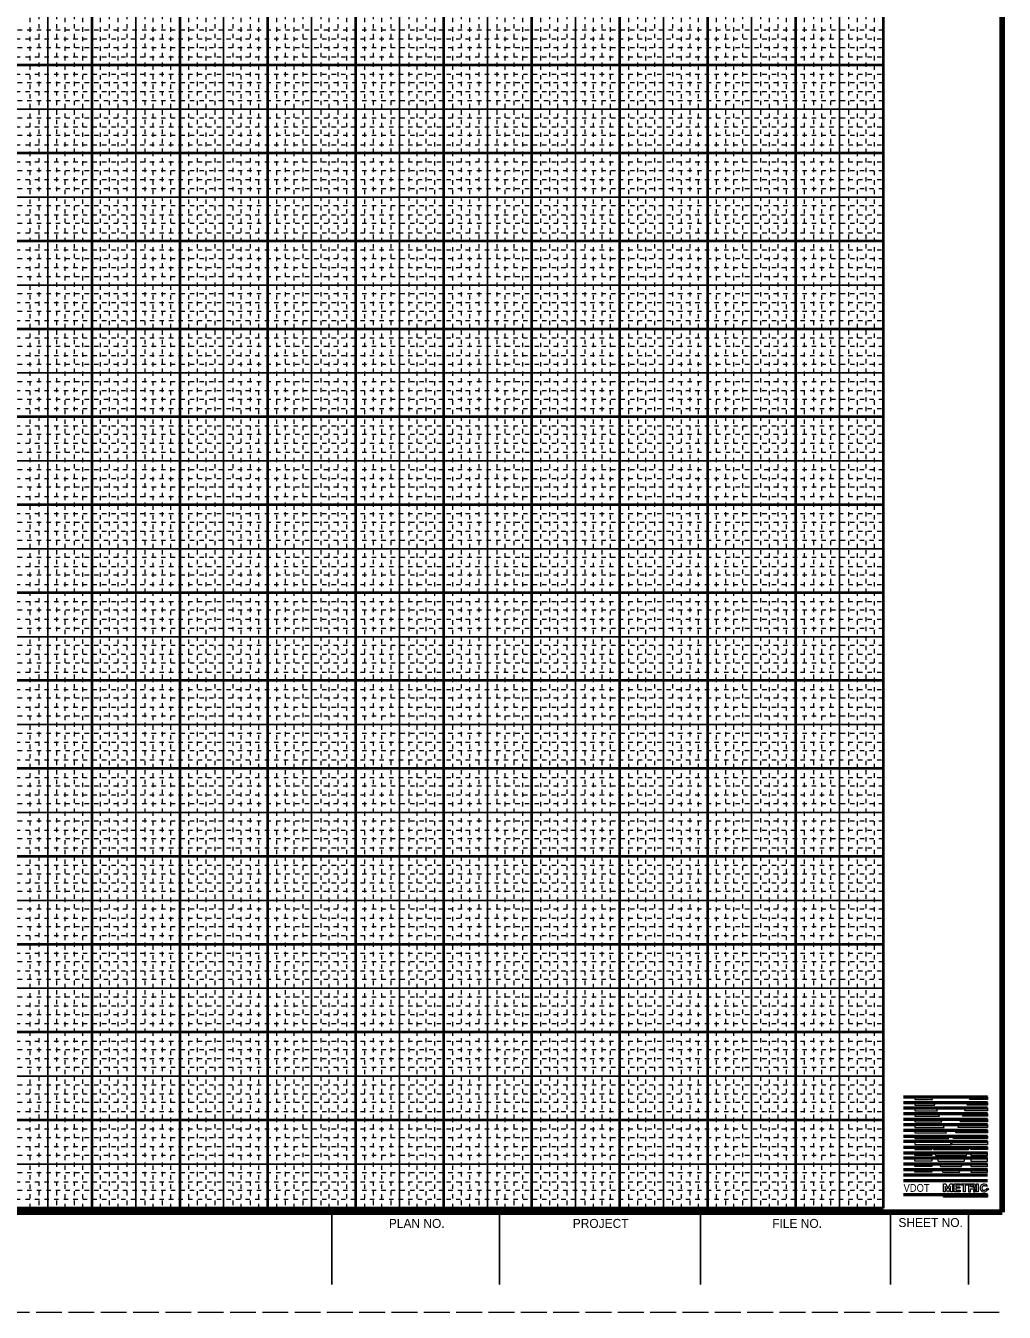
# Model space of a CAD drawing. Extents: x 224742 to 224831, y 224746 to 227695.
# Drawn here: x 224808.86 to 224831.11, y 226869.99 to 226899.26 of the extents above; entities that cross this region are included whole.
import ezdxf
from ezdxf.enums import TextEntityAlignment as Align

# ---------------------------------------------------------------- set-up
doc = ezdxf.new("R2010")
doc.units = 0
doc.header["$LTSCALE"] = 0.098
doc.header["$PDMODE"] = 32
doc.header["$PDSIZE"] = 0.049
doc.linetypes.add('DOTTED', pattern=[1.5, 0.3, -1.2])
doc.linetypes.add('LONG_DASHED', pattern=[7.5, 6, -1.5])
for name, color, linetype, lineweight in [('59', 7, 'DOTTED', 13), ('60', 7, 'Continuous', 40), ('61', 7, 'Continuous', 13), ('63', 7, 'LONG_DASHED', 13)]:
    doc.layers.add(name, color=color, linetype=linetype, lineweight=lineweight)

msp = doc.modelspace()

# ---------------------------------------------------------------- linework, layer by layer
at = {"layer": '59'}
for p, q in [((224808.9648, 226872.3649), (224808.9648, 226922.3649)), ((224809.1648, 226922.3649), (224809.1648, 226872.3649)), ((224809.5648, 226922.3649), (224809.5648, 226872.3649)), ((224809.7648, 226872.3649), (224809.7648, 226922.3649)), ((224809.9648, 226922.3649), (224809.9648, 226872.3649)), ((224810.1648, 226872.3649), (224810.1648, 226922.3649)), ((224810.5648, 226872.3649), (224810.5648, 226922.3649)), ((224810.7648, 226922.3649), (224810.7648, 226872.3649)), ((224810.9648, 226872.3649), (224810.9648, 226922.3649)), ((224811.1648, 226922.3649), (224811.1648, 226872.3649)), ((224811.5748, 226922.3649), (224811.5748, 226872.3649)), ((224811.7648, 226872.3649), (224811.7648, 226922.3649)), ((224811.9648, 226922.3649), (224811.9648, 226872.3649)), ((224812.1648, 226872.3649), (224812.1648, 226922.3649)), ((224812.5748, 226872.3649), (224812.5748, 226922.3649)), ((224812.7648, 226922.3649), (224812.7648, 226872.3649)), ((224812.9648, 226872.3649), (224812.9648, 226922.3649)), ((224813.1648, 226922.3649), (224813.1648, 226872.3649)), ((224813.5748, 226922.3649), (224813.5748, 226872.3649)), ((224813.7648, 226872.3649), (224813.7648, 226922.3649)), ((224813.9648, 226922.3649), (224813.9648, 226872.3649)), ((224814.1648, 226872.3649), (224814.1648, 226922.3649)), ((224814.5748, 226872.3649), (224814.5748, 226922.3649)), ((224814.7648, 226922.3649), (224814.7648, 226872.3649)), ((224814.9648, 226872.3649), (224814.9648, 226922.3649)), ((224815.1648, 226922.3649), (224815.1648, 226872.3649)), ((224815.5748, 226922.3649), (224815.5748, 226872.3649)), ((224815.7648, 226872.3649), (224815.7648, 226922.3649)), ((224815.9648, 226922.3649), (224815.9648, 226872.3649)), ((224816.1648, 226872.3649), (224816.1648, 226922.3649)), ((224816.5748, 226872.3649), (224816.5748, 226922.3649)), ((224816.7648, 226922.3649), (224816.7648, 226872.3649)), ((224816.9648, 226872.3649), (224816.9648, 226922.3649)), ((224817.1648, 226922.3649), (224817.1648, 226872.3649)), ((224817.5748, 226922.3649), (224817.5748, 226872.3649)), ((224817.7648, 226872.3649), (224817.7648, 226922.3649)), ((224817.9648, 226922.3649), (224817.9648, 226872.3649)), ((224818.1648, 226872.3649), (224818.1648, 226922.3649)), ((224818.5748, 226872.3649), (224818.5748, 226922.3649)), ((224818.7648, 226922.3649), (224818.7648, 226872.3649)), ((224818.9648, 226872.3649), (224818.9648, 226922.3649)), ((224819.1648, 226922.3649), (224819.1648, 226872.3649)), ((224819.5748, 226922.3649), (224819.5748, 226872.3649)), ((224819.7648, 226872.3649), (224819.7648, 226922.3649)), ((224819.9648, 226922.3649), (224819.9648, 226872.3649)), ((224820.1648, 226872.3649), (224820.1648, 226922.3649)), ((224820.5748, 226872.3649), (224820.5748, 226922.3649)), ((224820.7748, 226922.3649), (224820.7748, 226872.3649)), ((224820.9648, 226872.3649), (224820.9648, 226922.3649)), ((224821.1648, 226922.3649), (224821.1648, 226872.3649)), ((224821.5748, 226922.3649), (224821.5748, 226872.3649)), ((224821.7748, 226872.3649), (224821.7748, 226922.3649)), ((224821.9648, 226922.3649), (224821.9648, 226872.3649)), ((224822.1648, 226872.3649), (224822.1648, 226922.3649)), ((224822.5748, 226872.3649), (224822.5748, 226922.3649)), ((224822.7748, 226922.3649), (224822.7748, 226872.3649)), ((224822.9648, 226872.3649), (224822.9648, 226922.3649)), ((224823.1648, 226922.3649), (224823.1648, 226872.3649)), ((224823.5748, 226922.3649), (224823.5748, 226872.3649)), ((224823.7748, 226872.3649), (224823.7748, 226922.3649)), ((224823.9648, 226922.3649), (224823.9648, 226872.3649)), ((224824.1648, 226872.3649), (224824.1648, 226922.3649)), ((224824.5748, 226872.3649), (224824.5748, 226922.3649)), ((224824.7748, 226922.3649), (224824.7748, 226872.3649)), ((224824.9648, 226872.3649), (224824.9648, 226922.3649)), ((224825.1648, 226922.3649), (224825.1648, 226872.3649)), ((224825.5748, 226922.3649), (224825.5748, 226872.3649)), ((224825.7748, 226872.3649), (224825.7748, 226922.3649)), ((224825.9648, 226922.3649), (224825.9648, 226872.3649)), ((224826.1648, 226872.3649), (224826.1648, 226922.3649)), ((224826.5748, 226872.3649), (224826.5748, 226922.3649)), ((224826.7748, 226922.3649), (224826.7748, 226872.3649)), ((224826.9648, 226872.3649), (224826.9648, 226922.3649)), ((224827.1648, 226922.3649), (224827.1648, 226872.3649)), ((224827.5748, 226922.3649), (224827.5748, 226872.3649)), ((224827.7748, 226872.3649), (224827.7748, 226922.3649)), ((224827.9648, 226922.3649), (224827.9648, 226872.3649)), ((224828.1648, 226872.3649), (224828.1648, 226922.3649)), ((224828.3648, 226899.1649), (224748.3648, 226899.1649)), ((224748.3648, 226898.9649), (224828.3648, 226898.9649)), ((224828.3648, 226898.7649), (224748.3648, 226898.7649)), ((224748.3648, 226898.5549), (224828.3648, 226898.5549)), ((224748.3648, 226898.1649), (224828.3648, 226898.1649)), ((224828.3648, 226897.9649), (224748.3648, 226897.9649)), ((224748.3648, 226897.7649), (224828.3648, 226897.7649)), ((224828.3648, 226897.5549), (224748.3648, 226897.5549)), ((224828.3648, 226897.1649), (224748.3648, 226897.1649)), ((224748.3648, 226896.9649), (224828.3648, 226896.9649)), ((224828.3648, 226896.7649), (224748.3648, 226896.7649)), ((224748.3648, 226896.5549), (224828.3648, 226896.5549)), ((224748.3648, 226896.1649), (224828.3648, 226896.1649)), ((224828.3648, 226895.9649), (224748.3648, 226895.9649)), ((224748.3648, 226895.7649), (224828.3648, 226895.7649)), ((224828.3648, 226895.5549), (224748.3648, 226895.5549)), ((224828.3648, 226895.1649), (224748.3648, 226895.1649)), ((224748.3648, 226894.9649), (224828.3648, 226894.9649)), ((224828.3648, 226894.7649), (224748.3648, 226894.7649)), ((224748.3648, 226894.5549), (224828.3648, 226894.5549)), ((224748.3648, 226894.1649), (224828.3648, 226894.1649)), ((224828.3648, 226893.9649), (224748.3648, 226893.9649)), ((224748.3648, 226893.7649), (224828.3648, 226893.7649)), ((224828.3648, 226893.5549), (224748.3648, 226893.5549)), ((224828.3648, 226893.1649), (224748.3648, 226893.1649)), ((224748.3648, 226892.9649), (224828.3648, 226892.9649)), ((224828.3648, 226892.7649), (224748.3648, 226892.7649)), ((224748.3648, 226892.5549), (224828.3648, 226892.5549)), ((224748.3648, 226892.1649), (224828.3648, 226892.1649)), ((224828.3648, 226891.9649), (224748.3648, 226891.9649)), ((224748.3648, 226891.7649), (224828.3648, 226891.7649)), ((224828.3648, 226891.5549), (224748.3648, 226891.5549)), ((224828.3648, 226891.1649), (224748.3648, 226891.1649)), ((224748.3648, 226890.9649), (224828.3648, 226890.9649)), ((224828.3648, 226890.7649), (224748.3648, 226890.7649)), ((224748.3648, 226890.5549), (224828.3648, 226890.5549)), ((224748.3648, 226890.1649), (224828.3648, 226890.1649)), ((224828.3648, 226889.9649), (224748.3648, 226889.9649)), ((224748.3648, 226889.7649), (224828.3648, 226889.7649)), ((224828.3648, 226889.5549), (224748.3648, 226889.5549)), ((224828.3648, 226889.1649), (224748.3648, 226889.1649)), ((224748.3648, 226888.9649), (224828.3648, 226888.9649)), ((224828.3648, 226888.7649), (224748.3648, 226888.7649)), ((224748.3648, 226888.5549), (224828.3648, 226888.5549)), ((224748.3648, 226888.1649), (224828.3648, 226888.1649)), ((224828.3648, 226887.9649), (224748.3648, 226887.9649)), ((224748.3648, 226887.7649), (224828.3648, 226887.7649)), ((224828.3648, 226887.5549), (224748.3648, 226887.5549)), ((224828.3648, 226887.1649), (224748.3648, 226887.1649)), ((224748.3648, 226886.9649), (224828.3648, 226886.9649)), ((224828.3648, 226886.7649), (224748.3648, 226886.7649)), ((224748.3648, 226886.5549), (224828.3648, 226886.5549)), ((224748.3648, 226886.1649), (224828.3648, 226886.1649)), ((224828.3648, 226885.9649), (224748.3648, 226885.9649)), ((224748.3648, 226885.7649), (224828.3648, 226885.7649)), ((224828.3648, 226885.5549), (224748.3648, 226885.5549)), ((224828.3648, 226885.1649), (224748.3648, 226885.1649)), ((224748.3648, 226884.9649), (224828.3648, 226884.9649)), ((224828.3648, 226884.7649), (224748.3648, 226884.7649)), ((224748.3648, 226884.5549), (224828.3648, 226884.5549)), ((224748.3648, 226884.1649), (224828.3648, 226884.1649)), ((224828.3648, 226883.9649), (224748.3648, 226883.9649)), ((224748.3648, 226883.7649), (224828.3648, 226883.7649)), ((224828.3648, 226883.5549), (224748.3648, 226883.5549)), ((224828.3648, 226883.1649), (224748.3648, 226883.1649)), ((224748.3648, 226882.9649), (224828.3648, 226882.9649)), ((224828.3648, 226882.7649), (224748.3648, 226882.7649)), ((224748.3648, 226882.5649), (224828.3648, 226882.5649)), ((224748.3648, 226882.1649), (224828.3648, 226882.1649)), ((224828.3648, 226881.9649), (224748.3648, 226881.9649)), ((224748.3648, 226881.7649), (224828.3648, 226881.7649)), ((224828.3648, 226881.5649), (224748.3648, 226881.5649)), ((224828.3648, 226881.1649), (224748.3648, 226881.1649)), ((224748.3648, 226880.9649), (224828.3648, 226880.9649)), ((224828.3648, 226880.7649), (224748.3648, 226880.7649)), ((224748.3648, 226880.5649), (224828.3648, 226880.5649)), ((224748.3648, 226880.1649), (224828.3648, 226880.1649)), ((224828.3648, 226879.9649), (224748.3648, 226879.9649)), ((224748.3648, 226879.7649), (224828.3648, 226879.7649)), ((224828.3648, 226879.5649), (224748.3648, 226879.5649)), ((224828.3648, 226879.1649), (224748.3648, 226879.1649)), ((224748.3648, 226878.9649), (224828.3648, 226878.9649)), ((224828.3648, 226878.7649), (224748.3648, 226878.7649)), ((224748.3648, 226878.5649), (224828.3648, 226878.5649)), ((224748.3648, 226878.1649), (224828.3648, 226878.1649)), ((224828.3648, 226877.9649), (224748.3648, 226877.9649)), ((224748.3648, 226877.7649), (224828.3648, 226877.7649)), ((224828.3648, 226877.5649), (224748.3648, 226877.5649)), ((224828.3648, 226877.1649), (224748.3648, 226877.1649)), ((224748.3648, 226876.9649), (224828.3648, 226876.9649)), ((224828.3648, 226876.7649), (224748.3648, 226876.7649)), ((224748.3648, 226876.5649), (224828.3648, 226876.5649)), ((224748.3648, 226876.1649), (224828.3648, 226876.1649)), ((224828.3648, 226875.9649), (224748.3648, 226875.9649)), ((224748.3648, 226875.7649), (224828.3648, 226875.7649)), ((224828.3648, 226875.5649), (224748.3648, 226875.5649)), ((224828.3648, 226875.1649), (224748.3648, 226875.1649)), ((224748.3648, 226874.9649), (224828.3648, 226874.9649)), ((224828.3648, 226874.7649), (224748.3648, 226874.7649)), ((224748.3648, 226874.5649), (224828.3648, 226874.5649)), ((224748.3648, 226874.1649), (224828.3648, 226874.1649)), ((224828.3648, 226873.9649), (224748.3648, 226873.9649)), ((224748.3648, 226873.7649), (224828.3648, 226873.7649)), ((224828.3648, 226873.5649), (224748.3648, 226873.5649)), ((224828.3648, 226873.1649), (224748.3648, 226873.1649)), ((224748.3648, 226872.9649), (224828.3648, 226872.9649)), ((224828.3648, 226872.7649), (224748.3648, 226872.7649)), ((224748.3648, 226872.5649), (224828.3648, 226872.5649))]:
    msp.add_line(p, q, dxfattribs=at)
at = {"layer": '59', "linetype": 'Continuous', "lineweight": 25}
for p, q in [((224809.3648, 226872.3649), (224809.3648, 226922.3649)), ((224811.3648, 226872.3649), (224811.3648, 226922.3649)), ((224813.3648, 226872.3649), (224813.3648, 226922.3649)), ((224815.3648, 226872.3649), (224815.3648, 226922.3649)), ((224817.3648, 226872.3649), (224817.3648, 226922.3649)), ((224819.3648, 226872.3649), (224819.3648, 226922.3649)), ((224821.3648, 226872.3649), (224821.3648, 226922.3649)), ((224823.3648, 226872.3649), (224823.3648, 226922.3649)), ((224825.3648, 226872.3649), (224825.3648, 226922.3649)), ((224827.3648, 226872.3649), (224827.3648, 226922.3649)), ((224748.3648, 226897.3649), (224828.3648, 226897.3649)), ((224748.3648, 226895.3649), (224828.3648, 226895.3649)), ((224748.3648, 226893.3649), (224828.3648, 226893.3649)), ((224748.3648, 226891.3649), (224828.3648, 226891.3649)), ((224748.3648, 226889.3649), (224828.3648, 226889.3649)), ((224748.3648, 226887.3649), (224828.3648, 226887.3649)), ((224748.3648, 226885.3649), (224828.3648, 226885.3649)), ((224748.3648, 226883.3649), (224828.3648, 226883.3649)), ((224748.3648, 226881.3649), (224828.3648, 226881.3649)), ((224748.3648, 226879.3649), (224828.3648, 226879.3649)), ((224748.3648, 226877.3649), (224828.3648, 226877.3649)), ((224748.3648, 226875.3649), (224828.3648, 226875.3649)), ((224748.3648, 226873.3649), (224828.3648, 226873.3649))]:
    msp.add_line(p, q, dxfattribs=at)
at = {"layer": '60'}
for p, q in [((224810.3648, 226922.3649), (224810.3648, 226872.3649)), ((224812.3648, 226922.3649), (224812.3648, 226872.3649)), ((224814.3648, 226922.3649), (224814.3648, 226872.3649)), ((224816.3648, 226922.3649), (224816.3648, 226872.3649)), ((224818.3648, 226922.3649), (224818.3648, 226872.3649)), ((224820.3648, 226922.3649), (224820.3648, 226872.3649)), ((224822.3648, 226922.3649), (224822.3648, 226872.3649)), ((224824.3648, 226922.3649), (224824.3648, 226872.3649)), ((224826.3648, 226922.3649), (224826.3648, 226872.3649)), ((224828.3648, 226922.3649), (224828.3648, 226872.3649)), ((224828.3648, 226898.3649), (224748.3648, 226898.3649)), ((224828.3648, 226896.3649), (224748.3648, 226896.3649)), ((224828.3648, 226894.3649), (224748.3648, 226894.3649)), ((224828.3648, 226892.3649), (224748.3648, 226892.3649)), ((224828.3648, 226890.3649), (224748.3648, 226890.3649)), ((224828.3648, 226888.3649), (224748.3648, 226888.3649)), ((224828.3648, 226886.3649), (224748.3648, 226886.3649)), ((224828.3648, 226884.3649), (224748.3648, 226884.3649)), ((224828.3648, 226882.3649), (224748.3648, 226882.3649)), ((224828.3648, 226880.3649), (224748.3648, 226880.3649)), ((224828.3648, 226878.3649), (224748.3648, 226878.3649)), ((224828.3648, 226876.3649), (224748.3648, 226876.3649)), ((224828.3648, 226874.3649), (224748.3648, 226874.3649)), ((224828.3648, 226872.3649), (224748.3648, 226872.3649))]:
    msp.add_line(p, q, dxfattribs=at)
at = {"layer": '61', "lineweight": 158}
for p, q in [((224831.0648, 226926.1249), (224831.0648, 226872.2749)), ((224831.0648, 226872.2749), (224745.7148, 226872.2749))]:
    msp.add_line(p, q, dxfattribs=at)
at = {"layer": '61', "lineweight": 53}
for p, q in [((224828.8248, 226874.8949), (224830.7348, 226874.8949)), ((224828.8248, 226874.7649), (224830.7348, 226874.7649)), ((224828.8248, 226874.6449), (224830.7348, 226874.6449)), ((224828.8248, 226874.5149), (224830.7348, 226874.5149)), ((224828.8248, 226874.3849), (224830.7348, 226874.3849)), ((224828.8248, 226874.2649), (224830.7348, 226874.2649)), ((224828.8248, 226874.1349), (224830.7348, 226874.1349)), ((224828.8248, 226874.0049), (224830.7348, 226874.0049)), ((224828.8248, 226873.8849), (224830.7348, 226873.8849)), ((224828.8248, 226873.7549), (224830.7348, 226873.7549)), ((224828.8248, 226873.6249), (224830.7348, 226873.6249)), ((224828.8248, 226873.5049), (224830.7348, 226873.5049)), ((224828.8248, 226873.3749), (224830.7348, 226873.3749)), ((224828.8248, 226873.2449), (224830.7348, 226873.2449)), ((224828.8248, 226873.1249), (224830.7348, 226873.1249)), ((224828.8248, 226872.9949), (224830.7348, 226872.9949)), ((224828.8248, 226872.6749), (224830.7348, 226872.6749))]:
    msp.add_line(p, q, dxfattribs=at)
at = {"layer": '61'}
for p, q in [((224829.0848, 226874.0749), (224829.8048, 226874.0749)), ((224829.0848, 226873.9449), (224829.8548, 226873.9449)), ((224829.8848, 226873.8849), (224829.9048, 226873.8149)), ((224829.9348, 226873.8849), (224829.9048, 226873.8149)), ((224830.7348, 226873.9449), (224829.9548, 226873.9449)), ((224830.7348, 226874.0749), (224830.0148, 226874.0749)), ((224830.7348, 226872.8649), (224830.6848, 226872.8649)), ((224830.6948, 226872.7949), (224830.7348, 226872.7949))]:
    msp.add_line(p, q, dxfattribs=at)
at = {"layer": '61', "lineweight": 25}
for p, q in [((224831.0648, 226872.2749), (224815.8248, 226872.2749)), ((224815.8248, 226872.2749), (224815.8248, 226870.6249)), ((224831.0648, 226872.2749), (224815.8248, 226872.2749)), ((224819.6348, 226872.2749), (224819.6348, 226870.6249)), ((224824.2048, 226870.6249), (224824.2048, 226872.2749)), ((224828.5248, 226870.6249), (224828.5248, 226872.2749)), ((224830.3048, 226870.6249), (224830.3048, 226872.2749))]:
    msp.add_line(p, q, dxfattribs=at)
at = {"layer": '61'}
for points in [[(224829.0848, 226874.8949), (224829.0848, 226874.8349), (224829.4848, 226874.8349), (224829.4648, 226874.8949)], [(224829.0848, 226874.7649), (224829.0848, 226874.7049), (224829.5348, 226874.7049), (224829.5148, 226874.7649)], [(224830.7348, 226874.7649), (224830.7348, 226874.7049), (224830.2748, 226874.7049), (224830.2948, 226874.7649)], [(224830.7348, 226874.8949), (224830.7348, 226874.8349), (224830.3248, 226874.8349), (224830.3548, 226874.8949)], [(224829.0848, 226874.6449), (224829.0848, 226874.5749), (224829.5948, 226874.5749), (224829.5648, 226874.6449)], [(224829.0848, 226874.5149), (224829.0848, 226874.4549), (224829.6448, 226874.4549), (224829.6148, 226874.5149)], [(224830.7348, 226874.5149), (224830.7348, 226874.4549), (224830.1648, 226874.4549), (224830.1948, 226874.5149)], [(224830.7348, 226874.6449), (224830.7348, 226874.5749), (224830.2148, 226874.5749), (224830.2448, 226874.6449)], [(224829.0848, 226874.3849), (224829.0848, 226874.3249), (224829.6948, 226874.3249), (224829.6748, 226874.3849)], [(224829.0848, 226874.2649), (224829.0848, 226874.1949), (224829.7448, 226874.1949), (224829.7248, 226874.2649)], [(224829.0848, 226874.1349), (224829.0848, 226874.0749), (224829.8048, 226874.0749), (224829.7748, 226874.1349)], [(224830.7348, 226874.1349), (224830.7348, 226874.0749), (224830.0148, 226874.0749), (224830.0348, 226874.1349)], [(224830.7348, 226874.2649), (224830.7348, 226874.1949), (224830.0648, 226874.1949), (224830.0848, 226874.2649)], [(224830.7348, 226874.3849), (224830.7348, 226874.3249), (224830.1148, 226874.3249), (224830.1448, 226874.3849)], [(224829.0848, 226874.0049), (224829.0848, 226873.9449), (224829.8548, 226873.9449), (224829.8248, 226874.0049)], [(224829.0848, 226873.8849), (224829.0848, 226873.8149), (224829.9048, 226873.8149), (224829.8848, 226873.8849)], [(224830.7348, 226873.8849), (224830.7348, 226873.8149), (224829.9048, 226873.8149), (224829.9348, 226873.8849)], [(224830.7348, 226874.0049), (224830.7348, 226873.9449), (224829.9548, 226873.9449), (224829.9848, 226874.0049)], [(224829.0848, 226873.7549), (224829.0848, 226873.6949), (224829.4648, 226873.6949), (224829.4648, 226873.7549)], [(224829.0848, 226873.6249), (224829.4648, 226873.6249), (224829.4648, 226873.5649), (224829.0848, 226873.5649)], [(224829.4848, 226873.7549), (224829.5048, 226873.6949), (224830.3048, 226873.6949), (224830.3348, 226873.7549)], [(224829.5348, 226873.6249), (224829.5548, 226873.5649), (224830.2548, 226873.5649), (224830.2748, 226873.6249)], [(224830.7348, 226873.7549), (224830.7348, 226873.6949), (224830.3548, 226873.6949), (224830.3548, 226873.7549)], [(224830.7348, 226873.6249), (224830.3548, 226873.6249), (224830.3548, 226873.5649), (224830.7348, 226873.5649)], [(224829.0848, 226873.5049), (224829.4648, 226873.5049), (224829.4648, 226873.4349), (224829.0848, 226873.4349)], [(224829.0848, 226873.3749), (224829.4648, 226873.3749), (224829.4648, 226873.3149), (224829.0848, 226873.3149)], [(224829.0848, 226873.2449), (224829.4648, 226873.2449), (224829.4648, 226873.1849), (224829.0848, 226873.1849)], [(224829.5848, 226873.5049), (224829.6148, 226873.4349), (224830.2048, 226873.4349), (224830.2248, 226873.5049)], [(224829.6348, 226873.3749), (224829.6648, 226873.3149), (224830.1448, 226873.3149), (224830.1748, 226873.3749)], [(224829.6948, 226873.2449), (224829.7148, 226873.1849), (224830.0948, 226873.1849), (224830.1248, 226873.2449)], [(224830.7348, 226873.5049), (224830.3548, 226873.5049), (224830.3548, 226873.4349), (224830.7348, 226873.4349)], [(224830.7348, 226873.3749), (224830.3548, 226873.3749), (224830.3548, 226873.3149), (224830.7348, 226873.3149)], [(224830.7348, 226873.2449), (224830.3548, 226873.2449), (224830.3548, 226873.1849), (224830.7348, 226873.1849)], [(224829.7348, 226872.7349), (224829.7348, 226872.9149), (224829.7848, 226872.9149), (224829.8348, 226872.8049), (224829.8848, 226872.9149), (224829.9348, 226872.9149), (224829.9348, 226872.7349), (224829.8948, 226872.7349), (224829.8948, 226872.8549), (224829.8448, 226872.7349), (224829.8248, 226872.7349), (224829.7748, 226872.8549), (224829.7748, 226872.7349)], [(224829.7348, 226872.6749), (224830.7348, 226872.6749), (224830.7348, 226872.6149), (224829.7348, 226872.6149)], [(224829.9748, 226872.7349), (224829.9748, 226872.9149), (224830.1148, 226872.9149), (224830.1148, 226872.8849), (224830.0148, 226872.8849), (224830.0148, 226872.8449), (224830.1048, 226872.8449), (224830.1048, 226872.8149), (224830.0148, 226872.8149), (224830.0148, 226872.7749), (224830.1148, 226872.7749), (224830.1148, 226872.7349)], [(224830.1348, 226872.8849), (224830.1348, 226872.9149), (224830.2848, 226872.9149), (224830.2848, 226872.8849), (224830.2248, 226872.8849), (224830.2248, 226872.7349), (224830.1848, 226872.7349), (224830.1848, 226872.8849)], [(224830.3048, 226872.9149), (224830.3048, 226872.7349), (224830.3448, 226872.7349), (224830.3448, 226872.8049), (224830.3948, 226872.8049), (224830.3948, 226872.8049), (224830.4048, 226872.8049), (224830.4048, 226872.8049), (224830.4048, 226872.8049), (224830.4048, 226872.8049), (224830.4048, 226872.7949), (224830.4148, 226872.7949), (224830.4148, 226872.7849), (224830.4148, 226872.7749), (224830.4148, 226872.7549), (224830.4148, 226872.7549), (224830.4148, 226872.7449), (224830.4148, 226872.7349), (224830.4148, 226872.7349), (224830.4548, 226872.7349), (224830.4548, 226872.7449), (224830.4548, 226872.7449), (224830.4548, 226872.7449), (224830.4548, 226872.7549), (224830.4548, 226872.7849), (224830.4548, 226872.7949), (224830.4448, 226872.8049), (224830.4448, 226872.8149), (224830.4448, 226872.8149), (224830.4448, 226872.8149), (224830.4448, 226872.8149), (224830.4348, 226872.8149), (224830.4348, 226872.8249), (224830.4348, 226872.8249), (224830.4248, 226872.8249), (224830.4248, 226872.8249), (224830.4248, 226872.8249), (224830.3948, 226872.8449), (224830.3448, 226872.8449), (224830.3448, 226872.8849)], [(224830.3048, 226872.9149), (224830.3748, 226872.9149), (224830.3948, 226872.9149), (224830.3948, 226872.9149), (224830.4048, 226872.9149), (224830.4148, 226872.9149), (224830.4148, 226872.9149), (224830.4248, 226872.9149), (224830.4248, 226872.9149), (224830.4248, 226872.9149), (224830.4348, 226872.9149), (224830.4348, 226872.9049), (224830.4448, 226872.9049), (224830.4448, 226872.9049), (224830.4448, 226872.9049), (224830.4548, 226872.8949), (224830.4548, 226872.8949), (224830.4548, 226872.8949), (224830.4548, 226872.8849), (224830.4548, 226872.8849), (224830.4548, 226872.8749), (224830.4548, 226872.8649), (224830.4548, 226872.8649), (224830.4548, 226872.8549), (224830.4548, 226872.8549), (224830.4548, 226872.8549), (224830.4548, 226872.8449), (224830.4548, 226872.8449), (224830.4448, 226872.8449), (224830.4448, 226872.8449), (224830.4448, 226872.8349), (224830.4448, 226872.8349), (224830.4348, 226872.8349), (224830.4348, 226872.8349), (224830.4248, 226872.8249), (224830.4248, 226872.8249), (224830.3948, 226872.8449), (224830.3948, 226872.8449), (224830.4048, 226872.8449), (224830.4048, 226872.8449), (224830.4148, 226872.8449), (224830.4148, 226872.8549), (224830.4148, 226872.8549), (224830.4148, 226872.8549), (224830.4248, 226872.8649), (224830.4248, 226872.8649), (224830.4248, 226872.8649), (224830.4248, 226872.8749), (224830.4148, 226872.8749), (224830.4148, 226872.8749), (224830.4148, 226872.8749), (224830.4148, 226872.8849), (224830.4048, 226872.8849), (224830.4048, 226872.8849), (224830.3948, 226872.8849), (224830.3448, 226872.8849)], [(224830.4848, 226872.7349), (224830.4848, 226872.9149), (224830.5248, 226872.9149), (224830.5248, 226872.7349)]]:
    msp.add_lwpolyline(points, close=True, dxfattribs=at)
for radius, start, end in [(0.0894, 24.50501, 339.37361), (0.0518, 45.69947, 322.56629)]:
    msp.add_arc((224830.6538, 226872.8221), radius, start, end, dxfattribs=at)
msp.add_point((224830.7348, 226872.7949), dxfattribs=at)
at = {"layer": '63'}
msp.add_lwpolyline([(224831.1148, 226928.3949), (224742.2148, 226928.3949), (224742.2148, 226869.9949), (224831.1148, 226869.9949)], dxfattribs=at)

# ---------------------------------------------------------------- texts
at = {"layer": '61', "width": 0.9}
msp.add_text('VDOT', height=0.1778, dxfattribs=at).set_placement((224828.8248, 226872.7349))
at = {"layer": '61'}
for s, p in [('PLAN NO.', (224817.7557, 226871.9149)), ('PROJECT', (224821.9377, 226871.9149)), ('FILE NO.', (224826.405, 226871.9149)), ('SHEET NO.', (224829.4415, 226871.9341))]:
    msp.add_text(s, height=0.2032, dxfattribs=at).set_placement(p, align=Align.CENTER)

doc.saveas('drawing.dxf')
